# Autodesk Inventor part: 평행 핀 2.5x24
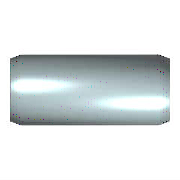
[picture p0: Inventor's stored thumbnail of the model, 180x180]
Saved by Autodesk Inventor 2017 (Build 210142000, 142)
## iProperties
IsCustomPart: 1
Created: 2012-02
Part Number: 평행 핀 2.5x24
Material: 강철, 연강
Description: 평행 핀
Document SubType Name: Modeling
Standard: KS B 1320
Designer: mduedu
Standards Organization: KS
Language: ko-KR
Size Designation: B 2.5 x  24
Categories: <MemberInstance><Categories><Category DisplayName="조임쇠" InternalName="e4da775c-781d-43d5-af7c-5136215cf5a6" Mnemonic="FSTN"><Category DisplayName="핀" InternalNa
Density: 1 g/cm^3
Appearance: 노란색
Author: mduedu
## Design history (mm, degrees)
sketch "스케치"
  geometry: C1 r 1.25 at (0, 0); 1 further point
  constraints: 1 centre point, 1 coincident
  dimensions: "d1" = 2.5 diameter of C1 (= NND)
extrude "본체" new body sketch "스케치" distance "d2" = 24 (= NLG); taper "d3" = 0 deg
chamfer "스케치2" distance "d8" = 0.4 (= PHH); stored, may be unused: angle "d9" = 15 deg (= FAWI), second distance "d12" = 0.4 (= PHH)
node "작업 평면1"
node "작업 평면2"
body "Solid1"
chamfer "모따기1" distance "d4" = 0.4 (= PHH); stored, may be unused: angle "d5" = 15 deg (= FAWI), second distance "d11" = 0.4 (= PHH)
other parameters: "NND" = 2.5 [user parameter; used in 1 equation term], "NLG" = 24 [user parameter; used in 1 equation term], "PHH" = 0.4 [user parameter; used in 4 equation terms], "FAWI" = 15 deg [user parameter; used in 2 equation terms], "d13" = 0, "d15" = 0, "d16" = 0, "KAH" = 0.3 [user parameter]
